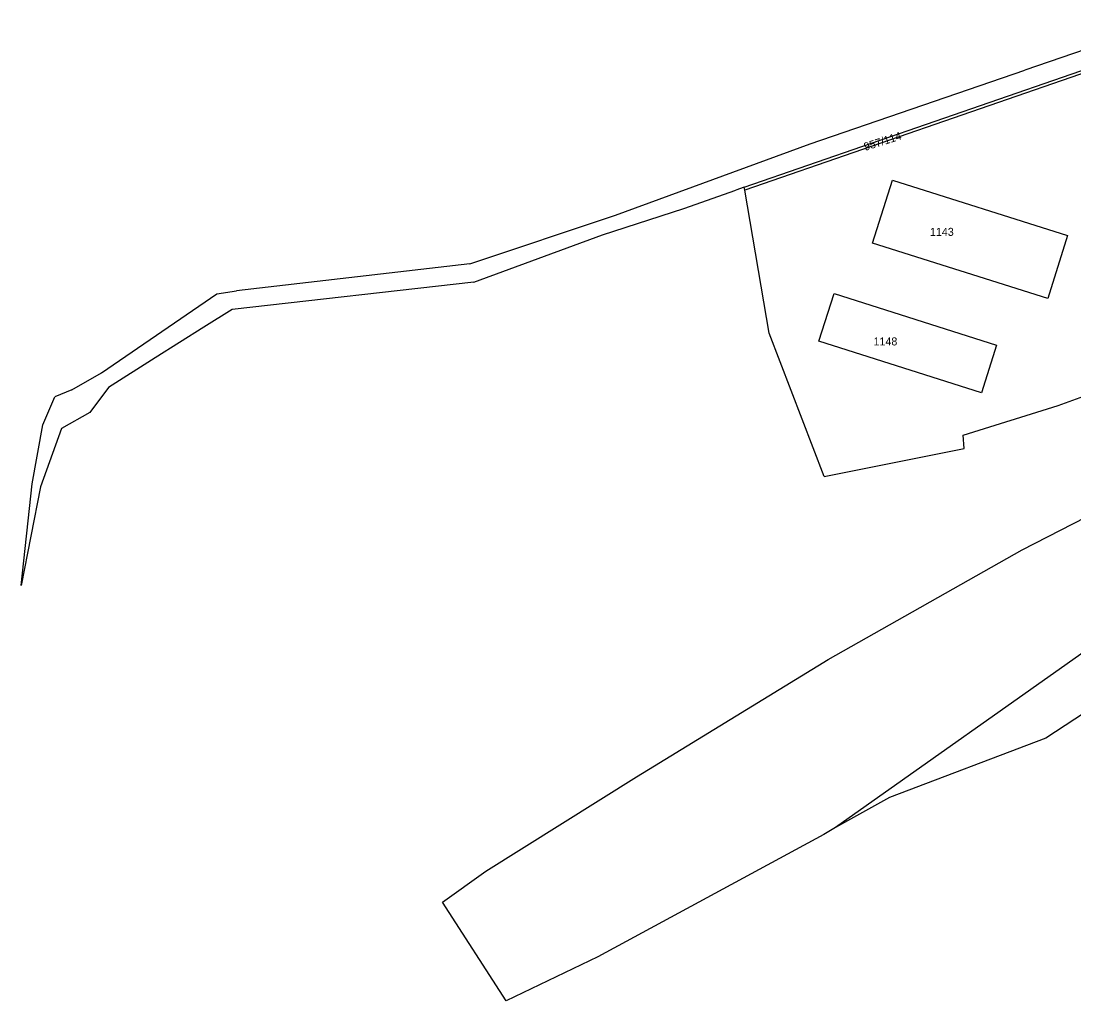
# Model space of a CAD drawing. Extents: x -752184 to -751416, y -1028299 to -1027836.
# Drawn here: x -752184.2 to -751921.2, y -1028298.9 to -1028054.1 of the extents above; entities that cross this region are included whole.
import ezdxf

# ---------------------------------------------------------------- set-up
doc = ezdxf.new("R2010")
doc.units = 0
for name, color, linetype in [('Vrstva 53', 7, 'Continuous'), ('Vrstva 55', 7, 'Continuous'), ('Vrstva 57', 7, 'Continuous')]:
    doc.layers.add(name, color=color, linetype=linetype)

msp = doc.modelspace()

# ---------------------------------------------------------------- linework, layer by layer
at = {"layer": 'Vrstva 53'}
for points in [[(-752078.91, -1028274.27), (-752068.08, -1028266.53), (-752030.45, -1028242.94), (-752025.93, -1028240.15), (-751982.6, -1028213.59), (-751934.1, -1028186.19), (-751914.9, -1028176.41)], [(-751864.36, -1028191.47), (-751928.16, -1028233.3), (-751967.27, -1028248.1), (-751980.73, -1028255.56), (-751983.66, -1028257.34), (-752040.12, -1028287.87), (-752063.02, -1028298.92)]]:
    msp.add_lwpolyline(points, dxfattribs=at)
at = {"layer": 'Vrstva 55'}
for p, q in [((-751881.38, -1028054.14), (-752003.38, -1028096.4)), ((-751913.74, -1028059.67), (-751933.45, -1028066.43)), ((-752003.56, -1028095.62), (-752005.66, -1028096.36)), ((-752003.38, -1028096.4), (-752003.56, -1028095.62)), ((-752072.09, -1028114.77), (-752130.41, -1028121.51)), ((-752138.59, -1028130.64), (-752150.71, -1028138.27)), ((-752171.57, -1028146.24), (-752175.83, -1028148.04)), ((-751983.58, -1028167.93), (-751948.62, -1028160.91)), ((-751882.55, -1028186.22), (-751980.73, -1028255.56)), ((-752030.45, -1028242.94), (-752025.93, -1028240.15)), ((-751980.73, -1028255.56), (-751983.66, -1028257.34)), ((-752063.02, -1028298.92), (-752078.91, -1028274.27))]:
    msp.add_line(p, q, dxfattribs=at)
for points in [[(-752003.56, -1028095.62), (-751908.15, -1028062.63), (-751881.38, -1028054.14)], [(-752072.09, -1028114.77), (-752035.67, -1028102.67), (-751987.04, -1028084.81), (-751933.45, -1028066.43)], [(-751927.67, -1028123.47), (-751971.5, -1028109.63), (-751966.53, -1028093.91), (-751922.77, -1028107.71), (-751927.67, -1028123.47)], [(-752071.11, -1028119.33), (-752038.95, -1028107.53), (-752018.63, -1028100.96), (-752005.66, -1028096.36)], [(-751983.58, -1028167.93), (-751997.32, -1028132.13), (-752003.38, -1028096.4)], [(-752071.11, -1028119.33), (-752131.47, -1028126.16), (-752138.59, -1028130.64)], [(-752171.57, -1028146.24), (-752164.12, -1028142.01), (-752135.34, -1028122.25), (-752130.41, -1028121.51)], [(-751981.1, -1028122.22), (-751940.47, -1028135.13), (-751944.23, -1028147.01), (-751984.89, -1028134.14), (-751981.1, -1028122.22)], [(-752150.71, -1028138.27), (-752162.4, -1028145.64), (-752167.07, -1028151.94)], [(-752184.23, -1028195.14), (-752181.48, -1028169.72), (-752178.76, -1028155.03), (-752175.83, -1028148.04)], [(-751948.62, -1028160.91), (-751948.85, -1028157.62), (-751925.12, -1028150.18), (-751915.97, -1028146.83)], [(-752167.07, -1028151.94), (-752174.15, -1028155.95), (-752179.37, -1028170.52), (-752184.23, -1028195.14)], [(-751837.73, -1028166.78), (-751864.36, -1028191.47), (-751928.16, -1028233.3), (-751967.27, -1028248.1), (-751980.73, -1028255.56)], [(-752025.93, -1028240.15), (-751982.6, -1028213.59), (-751934.1, -1028186.19), (-751914.9, -1028176.41), (-751903.43, -1028170.23)], [(-752078.91, -1028274.27), (-752068.08, -1028266.53), (-752030.45, -1028242.94)], [(-751983.66, -1028257.34), (-752040.12, -1028287.87), (-752063.02, -1028298.92)]]:
    msp.add_lwpolyline(points, dxfattribs=at)

# ---------------------------------------------------------------- texts
at = {"layer": 'Vrstva 57'}
msp.add_text('957/114', height=2, rotation=17.4652, dxfattribs=at).set_placement((-751973.3, -1028086.57))
for s, p in [('1143', (-751957.14, -1028107.8)), ('1148', (-751971.24, -1028135.17))]:
    msp.add_text(s, height=2, dxfattribs=at).set_placement(p)

doc.saveas('drawing.dxf')
